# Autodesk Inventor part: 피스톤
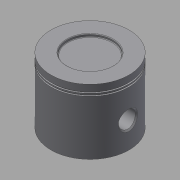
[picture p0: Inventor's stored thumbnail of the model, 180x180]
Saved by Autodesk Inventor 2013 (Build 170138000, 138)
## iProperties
Created: 2016-11
Part Number: 피스톤
Material: 강철, 탄소
Document SubType Name: Modeling
Designer: mduedu
Density: 7.87 g/cm^3
Mass: 273.372 g
Surface Area: 264.986 cm^2
Volume: 34.736 cm^3
Author: mduedu
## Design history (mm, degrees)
sketch "스케치1"
  geometry: C1 r 30 at (0, 0); 1 further point
  constraints: 1 centre point, 1 coincident
  dimensions: "d0" = 60 diameter of C1
extrude "돌출1" new body sketch "스케치1" distance "d1" = 50; taper "d2" = 0 deg
sketch "스케치2"
  geometry: C1 r 28 at (0, 0); 1 further point
  constraints: 1 centre point, 1 coincident
  dimensions: "d3" = 56 diameter of C1
extrude "돌출2" cut sketch "스케치2" distance "d4" = 45; taper "d5" = 0 deg
sketch "스케치3"
  geometry: L1 (30, 0)-(30, 50) reference; L2 (30, 45)-(29, 45); L3 (29, 45)-(29, 44); L4 (29, 44)-(30, 44); L5 (30, 44)-(30, 45); L6 (30, 43)-(29, 43); L7 (29, 43)-(29, 42); L8 (29, 42)-(30, 42); L9 (30, 42)-(30, 43); L10 (30, 50)-(-30, 50) reference; L11 (0, 50)-(0, 0)
  constraints: 18 end point, 4 parallel, 3 equal length, 3 perpendicular, 2 horizontal, 2 point on line, 1 midpoint
  dimensions: "d6" = 1 distance of L2.start L2.end; "d8" = 5 distance between parallel lines of L10 L2; "d9" = 1 distance between parallel lines of L6 L4
revolve "회전1" sketch "스케치3" stored, may be unused: angle "d10" = 90 deg
node "작업 평면1"
sketch "스케치4"
  geometry: C1 r 10 at (20, 0); C2 r 6.5 at (20, 0); 1 further point
  constraints: 2 centre point, 1 coincident, 1 horizontal alignment
  dimensions: "d12" = 20 diameter of C1; "d13" = 13 diameter of C2; "d14" = 20 distance of point (0, 0) C1.centre
extrude "돌출3" join sketch "스케치4" stored distance "d15" = 11.75; taper "d16" = 0 deg
extrude "돌출4" cut sketch "스케치4" stored distance "d17" = 72; taper "d18" = 0 deg
fillet "모깎기1" dims "d19" = 3
fillet "모깎기2" dims "d20" = 3
chamfer "모따기1" distance "d21" = 1; stored, may be unused: second distance "d22" = 2, angle "d23" = 45 deg
chamfer "모따기2" distance "d24" = 1; stored, may be unused: second distance "d25" = 2, angle "d26" = 45 deg
sketch "스케치5"
  geometry: C1 r 17.5 at (0, 0); 1 further point
  constraints: 1 centre point, 1 coincident
  dimensions: "d27" = 35 diameter of C1
extrude "돌출5" cut sketch "스케치5" distance "d28" = 2; taper "d29" = 0 deg
fillet "모깎기3" dims "d30" = 0.5
node "솔리드1"
mirror "대칭1"
